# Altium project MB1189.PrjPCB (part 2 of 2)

## Sheet Arduino_ Connectors.SchDoc: Arduino Uno connector
size A4; Date: 9/24/2014; Author: P.A.; CompanyName: STMicroelectronics; Organization: Microcontrollers Division; Address1: 12, Rue Jules HOROWITZ; Address2: 38019 Grenoble; Address3: FRANCE; DocumentNumber: 12; Revision: B-07; SheetNumber: 12; SheetTotal: 13; Project: STM32F469I-DISCO
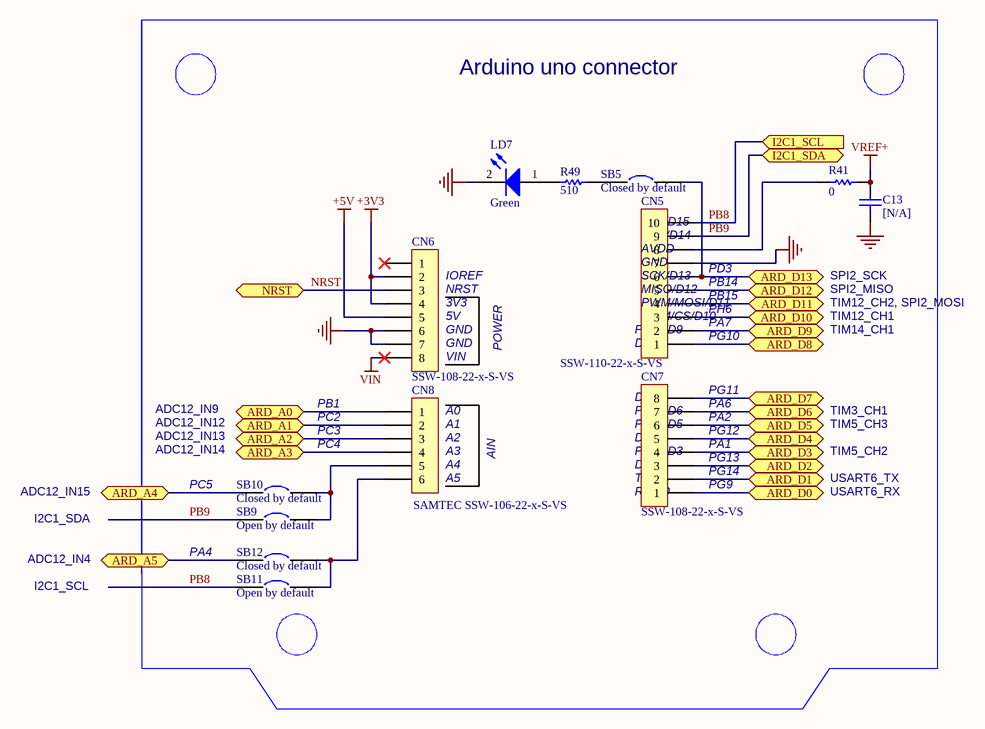
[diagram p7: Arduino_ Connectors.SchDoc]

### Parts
C13  [N/A]  [0603C]
CN5  SSW-110-22-x-S-VS  [SSW-110-22-X-S-VS]
CN6  SSW-108-22-x-S-VS  [SSW-108-22-X-S-VS]
CN7  SSW-108-22-x-S-VS  [SSW-108-22-X-S-VS]
CN8  SAMTEC SSW-106-22-x-S-VS  [SSW-106-22-X-S-VS]
LD7  Green  [0603D]
R41  0  [0603R]
R49  510  [0603R]
SB5  Closed by default  [SB_0603]
SB9  Open by default  [SB_0603]
SB10  Closed by default  [SB_0603]
SB11  Open by default  [SB_0603]
SB12  Closed by default  [SB_0603]

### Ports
ARD_A0 (bidir), ARD_A1 (bidir), ARD_A2 (bidir), ARD_A3 (bidir), ARD_A4 (bidir), ARD_A5 (bidir), ARD_D0 (bidir), ARD_D1 (bidir), ARD_D2 (bidir), ARD_D3 (bidir), ARD_D4 (bidir), ARD_D5 (bidir), ARD_D6 (bidir), ARD_D7 (bidir), ARD_D8 (bidir), ARD_D9 (bidir), ARD_D10 (bidir), ARD_D11 (bidir), ARD_D12 (bidir), ARD_D13 (bidir), I2C1_SCL (in), I2C1_SDA (bidir), NRST (bidir)

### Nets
+3V3: CN6.2 CN6.4
+5V: CN6.5
GND: C13.1 CN5.7 CN6.6 CN6.7 LD7.2(K)
VIN: CN6.8
VREF+: C13.2 R41.1
NRST: CN6.3 ; port NRST
PA1: CN7.4 ; port ARD_D3
PA2: CN7.6 ; port ARD_D5
PA4: SB12.1 ; port ARD_A5
PA6: CN7.7 ; port ARD_D6
PA7: CN5.2 ; port ARD_D9
PB1: CN8.1 ; port ARD_A0
PB8: CN5.10 SB11.1 ; port I2C1_SCL  [project net I2C1_SCL]
PB9: CN5.9 SB9.1 ; port I2C1_SDA  [project net I2C1_SDA]
PB14: CN5.5 ; port ARD_D12
PB15: CN5.4 ; port ARD_D11
PC2: CN8.2 ; port ARD_A1
PC3: CN8.3 ; port ARD_A2
PC4: CN8.4 ; port ARD_A3
PC5: SB10.1 ; port ARD_A4
PD3: CN5.6 SB5.2 ; port ARD_D13
PG9: CN7.1 ; port ARD_D0
PG10: CN5.1 ; port ARD_D8
PG11: CN7.8 ; port ARD_D7
PG12: CN7.5 ; port ARD_D4
PG13: CN7.3 ; port ARD_D2
PG14: CN7.2 ; port ARD_D1
PH6: CN5.3 ; port ARD_D10
NetCN5_8: CN5.8 R41.2
NetCN8_5: CN8.5 SB9.2 SB10.2
NetCN8_6: CN8.6 SB11.2 SB12.2
NetLD7_1: LD7.1(A) R49.2
NetR49_1: R49.1 SB5.1

Not connected (* = marked no-connect by the designer): CN6 1*

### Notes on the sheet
- Arduino uno connector
- (near CN5) SDA/D14
- SCL/D15
- (near CN5) AVDD
- (near CN6) IOREF
- (near CN6) NRST
- (near CN6) 3V3
- (near CN5) SCK/D13
- (near CN5) MISO/D12
- (near CN5) PWM/MOSI/D11
- (near CN5) GND
- (near CN5) PH6
- (near CN5) PB15
- (near CN5) PB14
- (near CN5) PD3
- TIM12_CH2, SPI2_MOSI
- SPI2_MISO
- SPI2_SCK
- (near CN6) 5V
- (near CN6) GND
- (near CN6) VIN
- POWER
- (near CN5) D8
- (near CN5) PWM/D9
- (near CN5) PWM/CS/D10
- (near CN5) PG10
- (near CN5) PA7
- TIM14_CH1
- TIM12_CH1
- ADC12_IN14
- ADC12_IN13
- ADC12_IN12
- ADC12_IN9
- PB1
- PC2
- PC3
- PC4
- (near CN8) A0
- (near CN8) A1
- (near CN8) A2
- (near CN7) D4
- (near CN7) PWM/D5
- (near CN7) PWM/D6
- (near CN7) D7
- (near CN7) PA1
- (near CN7) PG12
- (near CN7) PA2
- (near CN7) PA6
- PG11
- TIM5_CH3
- TIM3_CH1
- ADC12_IN15
- I2C1_SDA
- PC5
- (near CN8) A3
- (near CN8) A4
- (near CN8) A5
- AIN
- (near CN7) RX/D0
- (near CN7) TX/D1
- (near CN7) D2
- (near CN7) PWM/D3
- (near CN7) PG9
- (near CN7) PG14
- (near CN7) PG13
- USART6_RX
- USART6_TX
- TIM5_CH2
- ADC12_IN4
- PA4
- I2C1_SCL

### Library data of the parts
C13 = Cap: Capacitor; Value: 10nF; Ordered by: Subcon; Fitted: NO
CN5 = Header 10X1_Female: Header, 10-Pin, Single row,female; Manuf_1: SAMTEC; Ordered by: Subcon; Silkscreen: pin names as in schematic
CN6 CN7 = Header 8X1_Female: Header, 8-Pin, Single row,female; Manuf_1: SAMTEC; Ordered by: Subcon; Silkscreen: pin names as in schematic
CN8 = Header 6X1_Female: Header, 6-Pin, Single row,female SMD; Ordered by: Subcon; Silkscreen: pin names as in schematic
LD7 = LED2: Typical RED, GREEN, YELLOW, AMBER GaAs LED; Ordered by: Subcon; ECCN_US/EU: EAR99/NEC
R41 R49 = Res1: Resistor; Value: 1K; Ordered by: Subcon
SB5 SB10 SB12 = Circuit Breaker: Ordered by: Subcon; Comments: Solder bridge
SB9 SB11 = Circuit Breaker: Ordered by: Subcon; Comments: Solder bridge; Fitted: NO

## Sheet DSI_LCD.SchDoc: 4 inch DSI LCD board
size A4; Date: 9/24/2014; Author: P.A.; CompanyName: STMicroelectronics; Organization: Microcontrollers Division; Address1: 12, Rue Jules HOROWITZ; Address2: 38019 Grenoble; Address3: FRANCE; DocumentNumber: 8; Revision: B-07; SheetNumber: 8; SheetTotal: 13; Project: STM32F469I-DISCO
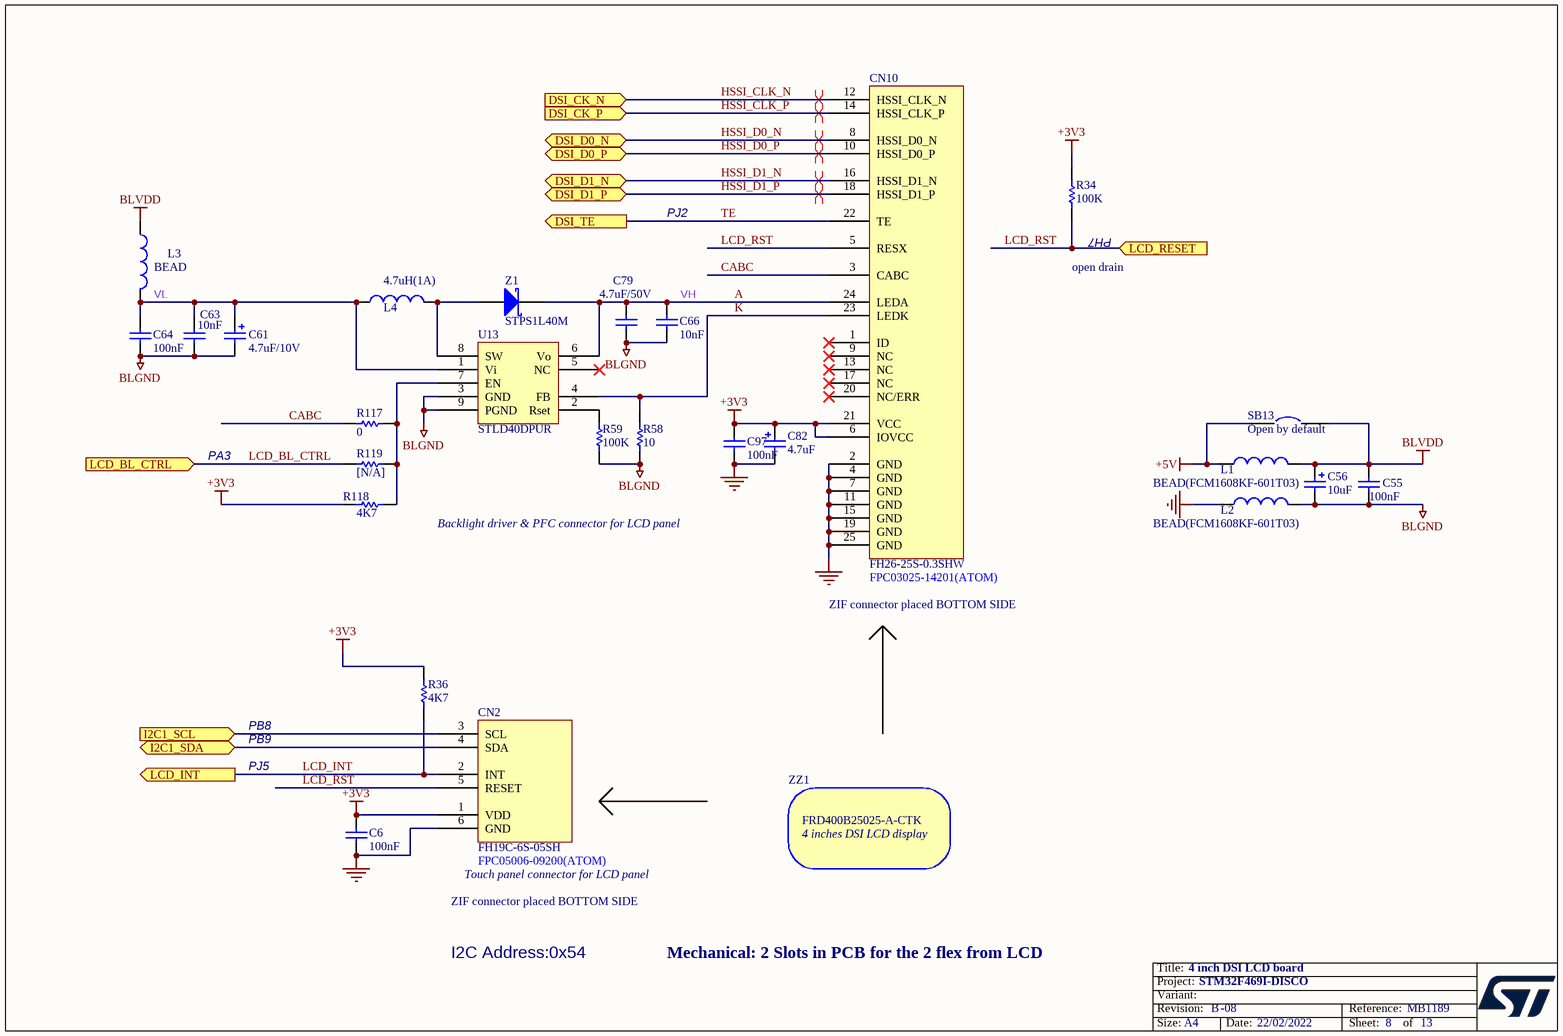
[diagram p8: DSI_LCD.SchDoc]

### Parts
C6  100nF  [0402C]
C55  100nF  [0402C]
C56  10uF  [TAN-A]
C61  4.7uF/10V  [1206C]
C63  10nF  [0603C]
C64  100nF  [0402C]
C66  10nF  [0603C]
C79  4.7uF/50V  [1206C]
C82  4.7uF  [TAN-A]
C97  100nF  [0402C]
CN2  FH19C-6S-05SH  [FH19C-6S-0R5SH_FPC_CPT]
CN10  FH26-25S-0.3SHW  [FPC25_FPC03025-1420]
L1  BEAD(FCM1608KF-601T03)  [0603L]
L2  BEAD(FCM1608KF-601T03)  [0603L]
L3  BEAD  [0603L]
L4  4.7uH(1A)  [1210L]
R34  100K  [0402R]
R36  4K7  [0603R]
R58  10  [0603R]
R59  100K  [0603R]
R117  0  [0603R]
R118  4K7  [0603R]
R119  [N/A]  [0603R]
SB13  Open by default  [SB_0603]
U13  STLD40DPUR  [SON8_0R65_3X3]
Z1  STPS1L40M  [DO-216AA]
ZZ1  FRD400B25025-A-CTK

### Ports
DSI_CK_N (in), DSI_CK_P (in), DSI_D0_N (bidir), DSI_D0_P (bidir), DSI_D1_N (bidir), DSI_D1_P (bidir), DSI_TE (out), I2C1_SCL (in), I2C1_SDA (bidir), LCD_BL_CTRL (in), LCD_INT (out), LCD_RESET (in)

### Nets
+3V3: C6.2 C82.1 C97.2 CN2.1(VDD) CN10.6(IOVCC) CN10.21(VCC) R34.1 R36.1 R118.2
+5V: L1.1 SB13.1
BLGND: C55.2 C56.2 C61.2 C63.1 C64.1 C66.1 C79.2 L2.2 R58.1 R59.2 U13.3(GND) U13.9(PGND)
BLVDD: C55.1 C56.1 L1.2 L3.1 SB13.2
GND: C6.1 C82.2 C97.1 CN2.6(GND) CN10.2(GND) CN10.4(GND) CN10.7(GND) CN10.11(GND) CN10.15(GND) CN10.19(GND) CN10.25(GND) L2.1
A: C66.2 C79.1 CN10.24(LEDA) U13.6(Vo) Z1.2(K)  [also labelled VH]
CABC: CN10.3(CABC) R117.2
HSSI_CLK_N: CN10.12(HSSI_CLK_N) ; port DSI_CK_N
HSSI_CLK_P: CN10.14(HSSI_CLK_P) ; port DSI_CK_P
HSSI_D0_N: CN10.8(HSSI_D0_N) ; port DSI_D0_N
HSSI_D0_P: CN10.10(HSSI_D0_P) ; port DSI_D0_P
HSSI_D1_N: CN10.16(HSSI_D1_N) ; port DSI_D1_N
HSSI_D1_P: CN10.18(HSSI_D1_P) ; port DSI_D1_P
I2C1_SCL: CN2.3(SCL) ; port I2C1_SCL
I2C1_SDA: CN2.4(SDA) ; port I2C1_SDA
K: CN10.23(LEDK) R58.2 U13.4(FB)
LCD_BL_CTRL: R119.2 ; port LCD_BL_CTRL
LCD_INT: CN2.2(INT) R36.2 ; port LCD_INT
LCD_RST: CN2.5(RESET) CN10.5(RESX) R34.2 ; port LCD_RESET
TE: CN10.22(TE) ; port DSI_TE  [project net PJ2]
VL: C61.1 C63.2 C64.2 L3.2 L4.1 U13.1(Vi)
NetL4_2: L4.2 U13.8(SW) Z1.1(A)
NetR59_1: R59.1 U13.2(Rset)
NetR117_1: R117.1 R118.1 R119.1 U13.7(EN)

Not connected (* = marked no-connect by the designer): CN10 1(ID)* 9(NC)* 13(NC)* 17(NC)* 20(NC/ERR)*; U13 5(NC)*

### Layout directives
differential pair: HSSI_CLK_N, HSSI_CLK_P, HSSI_D0_N, HSSI_D0_P, HSSI_D1_N, HSSI_D1_P

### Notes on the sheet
- PJ2
- (near R34) PH7
- open drain
- PA3
- Backlight driver & PFC connector for LCD panel
- (near CN10) FPC03025-14201(ATOM)
- ZIF connector placed BOTTOM SIDE
- PB9
- PB8
- PJ5
- (near ZZ1) 4 inches DSI LCD display
- (near CN2) Touch panel connector for LCD panel
- (near CN2) FPC05006-09200(ATOM)
- I2C Address:0x54
- Mechanical: 2 Slots in PCB for the 2 flex from LCD

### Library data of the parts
C6 C63 C64 C66 C79 C97 = CAP: Capacitor; Value: 100pF; Ordered by: Subcon
C55 = Cap: Capacitor; Value: 10nF; Ordered by: Subcon
C56 = Cap Pol1: Polarized Capacitor (Radial); Ordered by: Subcon
C61 C82 = Cap Pol1: Polarized Capacitor (Radial); Value: 100pF; Ordered by: Subcon
CN2 = FH19C-6S-05SH: ZIF connector placed bottom side; Manuf_1: ATOM; Manuf_2: Hirose; Manuf_Part_1: FPC05006-09200; Ordered by: Subcon; Silkscreen: TS
CN10 = FH26-25S-0.3SHW: ZIF connector placed bottom side; Manuf_1: ATOM; Manuf_Part_1: FPC03025-14201; Manuf_2: Hirose; Ordered by: Subcon; Comments: Hirose FH26-25S-0.3SHW; Silkscreen: DSI LCD
L1-L4 = Inductor: Value: 100uH; Ordered by: Subcon
R34 R36 R58 R59 R117 R118 = Res1: Resistor; Value: 1K; Ordered by: Subcon
R119 = Res1: Resistor; Value: 1K; Ordered by: Subcon; Fitted: NO
SB13 = Circuit Breaker: as SB9 on sheet Arduino_ Connectors
U13 = STLD40DPMR: Ordered by: ST; Ref St: 9176009; ECCN_US/EU: EAR99/NEC
Z1 = D Schottky: Schottky Diode; Code - JEDEC: DO-214-AA; Ordered by: ST; Ref St: 9151085; ECCN_US/EU: EAR99/NEC
ZZ1 = BoM_Item: 4 inches DSI LCD with touch screen; Manuf_1: Frida; Ordered by: Subcon; Comments: 4 inches DSI LCD display; ECCN_US/EU: EAR99/NEC

## Sheet QSPI.SchDoc: QSPI
size A4; Date: 9/24/2014; Author: P.A.; CompanyName: STMicroelectronics; Organization: Microcontrollers Division; Address1: 12, Rue Jules HOROWITZ; Address2: 38019 Grenoble; Address3: FRANCE; DocumentNumber: 10; Revision: B-07; SheetNumber: 10; SheetTotal: 13; Project: STM32F469I-DISCO
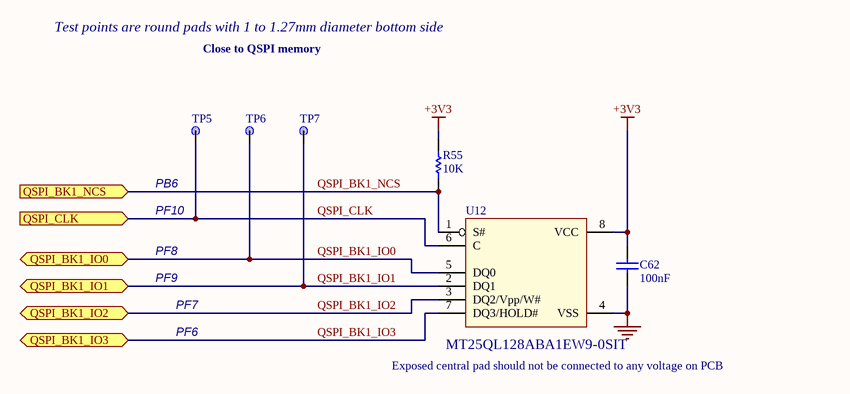
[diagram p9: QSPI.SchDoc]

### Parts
C62  100nF  [0402C]
R55  10K  [0402R]
TP5  TP  [TP_C40]  (value not drawn)
TP6  TP  [TP_C40]  (value not drawn)
TP7  TP  [TP_C40]  (value not drawn)
U12  MT25QL128ABA1EW9-0SIT  [DFN8_1R27_6X8_TP4R8X5R8]

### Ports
QSPI_BK1_IO0 (bidir), QSPI_BK1_IO1 (bidir), QSPI_BK1_IO2 (bidir), QSPI_BK1_IO3 (bidir), QSPI_BK1_NCS (in), QSPI_CLK (in)

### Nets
+3V3: C62.1 R55.2 U12.8(VCC)
GND: C62.2 U12.4(VSS)
QSPI_BK1_IO0: TP6.1 U12.5(DQ0) ; port QSPI_BK1_IO0  [project net PF8]
QSPI_BK1_IO1: TP7.1 U12.2(DQ1) ; port QSPI_BK1_IO1  [project net PF9]
QSPI_BK1_IO2: U12.3(DQ2/Vpp/W#) ; port QSPI_BK1_IO2  [project net PF7]
QSPI_BK1_IO3: U12.7(DQ3/HOLD#) ; port QSPI_BK1_IO3  [project net PF6]
QSPI_BK1_NCS: R55.1 U12.1(S#) ; port QSPI_BK1_NCS  [project net PB6]
QSPI_CLK: TP5.1 U12.6(C) ; port QSPI_CLK  [project net PF10]

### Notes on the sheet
- Test points are round pads with 1 to 1.27mm diameter bottom side
- Close to QSPI memory
- (near TP5) PB6
- PF10
- PF8
- PF9
- PF7
- PF6
- (near U12) Exposed central pad should not be connected to any voltage on PCB

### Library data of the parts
C62 = Cap: as C55 on sheet DSI_LCD
R55 = Res_10K_1%_0402: Resistor; Manuf_Part_1: RC0402FR-0710KL; Manuf_1: YAGEO; Ordered by: Subcon
TP5-TP7 = TP: Ordered by: Subcon
U12 = N25Q128A13EF840E: 128Mb, 3V, Multiple I/O Serial Flash Memory, Quad/Dual; Manuf_1: MICRON; Ordered by: Subcon

## Sheet AUDIO2.SchDoc: Audio Codec and Microphone MEMS
size A4; Date: 9/24/2014; Author: P.A.; CompanyName: STMicroelectronics; Organization: Microcontrollers Division; Address1: 12, Rue Jules HOROWITZ; Address2: 38019 Grenoble; Address3: FRANCE; DocumentNumber: 7; Revision: B-07; SheetNumber: 7; SheetTotal: 13; Project: STM32F469I-DISCO
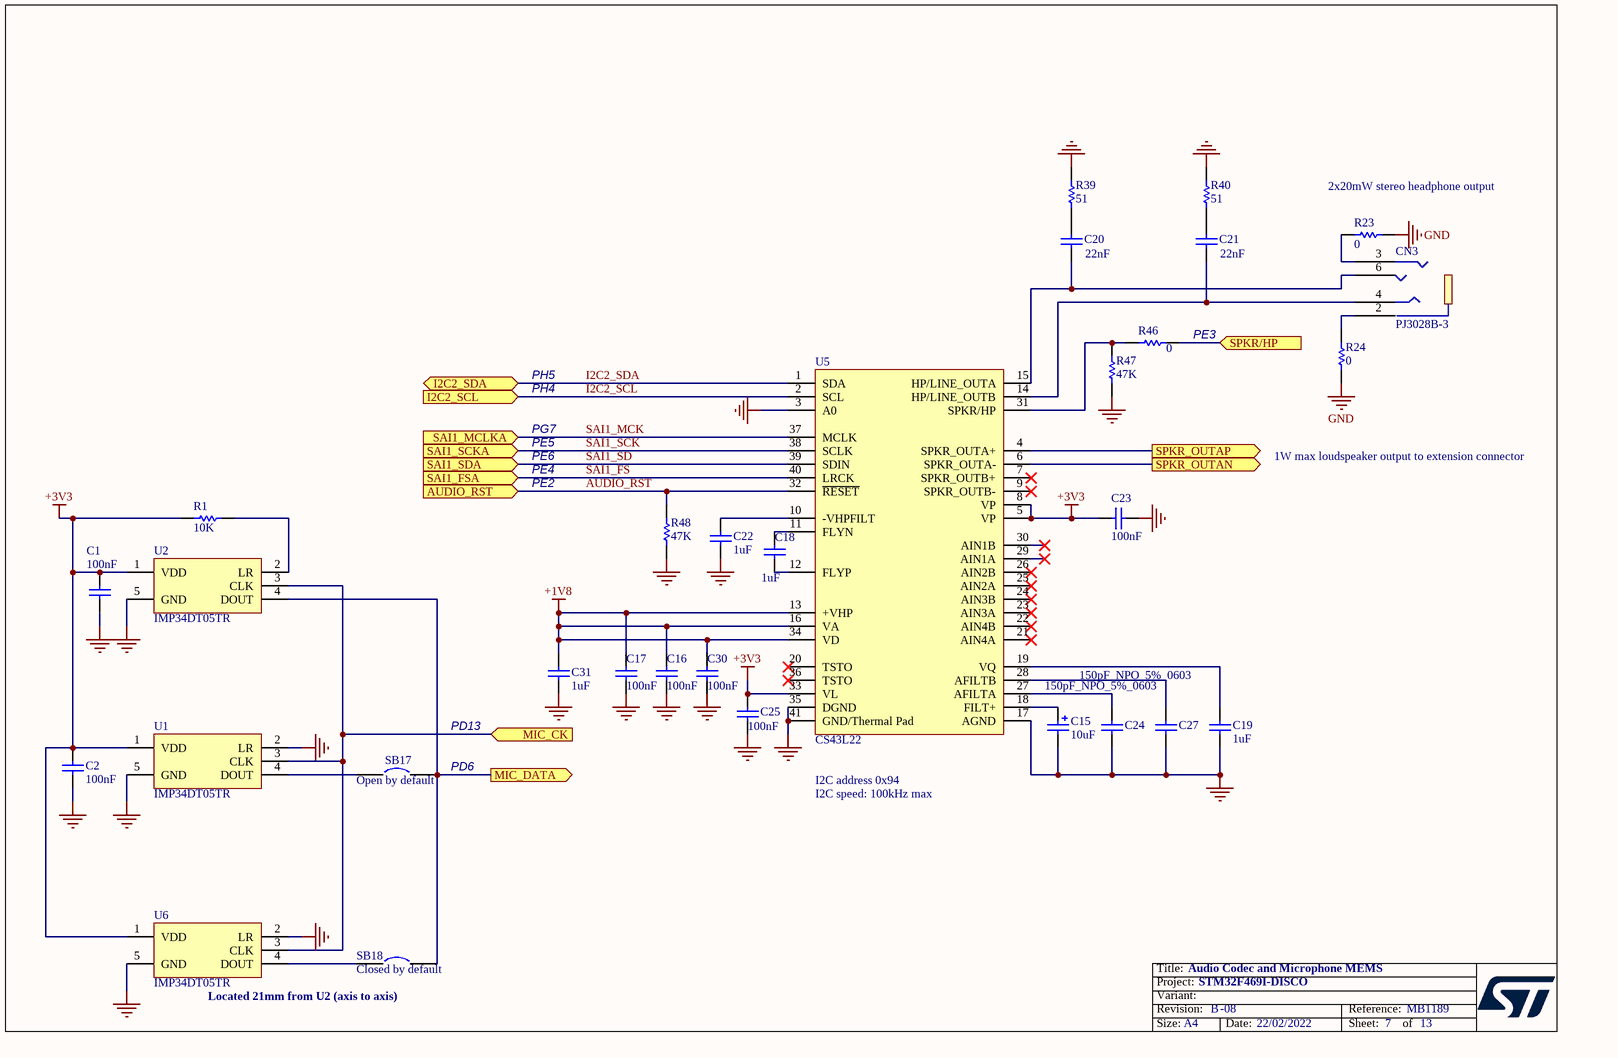
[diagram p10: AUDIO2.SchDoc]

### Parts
C1  100nF  [0402C]
C2  100nF  [0402C]
C15  10uF  [TAN-A]
C16  100nF  [0402C]
C17  100nF  [0402C]
C18  1uF  [0603C]
C19  1uF  [0603C]
C20  22nF  [0603C]
C21  22nF  [0603C]
C22  1uF  [0603C]
C23  100nF  [0402C]
C24  150pF_NPO_5%_0603  [0603C]
C25  100nF  [0402C]
C27  150pF_NPO_5%_0603  [0603C]
C30  100nF  [0402C]
C31  1uF  [0603C]
CN3  PJ3028B-3  [PJ3028B]
R1  10K  [0603R]
R23  0  [0603R]
R24  0  [0603R]
R39  51  [0402R]
R40  51  [0402R]
R46  0  [0603R]
R47  47K  [0603R]
R48  47K  [0603R]
SB17  Open by default  [SB_0603]
SB18  Closed by default  [SB_0603]
U1  IMP34DT05TR  [MP34DT01TR]
U2  IMP34DT05TR  [MP34DT01TR]
U5  CS43L22  [QFN40_0R5_6X6]
U6  IMP34DT05TR  [MP34DT01TR]

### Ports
AUDIO_RST (in), I2C2_SCL (in), I2C2_SDA (bidir), MIC_CK (in), MIC_DATA (out), SAI1_FSA (in), SAI1_MCLKA (in), SAI1_SCKA (in), SAI1_SDA (in), SPKR/HP (in), SPKR_OUTAN (out), SPKR_OUTAP (out)

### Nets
+1V8: C16.1 C17.1 C30.1 C31.1 U5.13(+VHP) U5.16(VA) U5.34(VD)
+3V3: C1.2 C2.2 C23.2 C25.1 R1.2 U1.1(VDD) U2.1(VDD) U5.5(VP) U5.8(VP) U5.33(VL) U6.1(VDD)
GND: C1.1 C2.1 C15.2 C16.2 C17.2 C19.1 C22.1 C23.1 C24.1 C25.2 C27.1 C30.2 C31.2 R23.2 R24.2 R39.2 R40.2 R47.2 R48.1 U1.2(LR) U1.5(GND) U2.5(GND) U5.3(A0) U5.17(AGND) U5.35(DGND) U5.41(GND/Thermal_Pad) U6.2(LR) U6.5(GND)
AUDIO_RST: R48.2 U5.32(~{RESET}) ; port AUDIO_RST
I2C2_SCL: U5.2(SCL) ; port I2C2_SCL
I2C2_SDA: U5.1(SDA) ; port I2C2_SDA
PD6: SB17.2 SB18.2 U2.4(DOUT) ; port MIC_DATA
PE3: R46.2 ; port SPKR/HP
SAI1_FS: U5.40(LRCK) ; port SAI1_FSA  [project net PE4]
SAI1_MCK: U5.37(MCLK) ; port SAI1_MCLKA  [project net PG7]
SAI1_SCK: U5.38(SCLK) ; port SAI1_SCKA  [project net PE5]
SAI1_SD: U5.39(SDIN) ; port SAI1_SDA  [project net PE6]
NetC15_1: C15.1 U5.18(FILT+)
NetC18_1: C18.1 U5.11(FLYN)
NetC18_2: C18.2 U5.12(FLYP)
NetC19_2: C19.2 U5.19(VQ)
NetC20_1: C20.1 CN3.6 U5.15(HP/LINE_OUTA)
NetC20_2: C20.2 R39.1
NetC21_1: C21.1 CN3.4 U5.14(HP/LINE_OUTB)
NetC21_2: C21.2 R40.1
NetC22_2: C22.2 U5.10(-VHPFILT)
NetC24_2: C24.2 U5.27(AFILTA)
NetC27_2: C27.2 U5.28(AFILTB)
NetCN3_2: CN3.2 R24.1
NetCN3_3: CN3.3 R23.1
NetCN12_15: U5.6(SPKR_OUTA-) ; port SPKR_OUTAN
NetCN12_16: U5.4(SPKR_OUTA+) ; port SPKR_OUTAP
NetR1_1: R1.1 U2.2(LR)
NetR46_1: R46.1 R47.1 U5.31(SPKR/HP)
NetR87_1: U1.3(CLK) U2.3(CLK) U6.3(CLK) ; port MIC_CK
NetSB17_1: SB17.1 U1.4(DOUT)
NetSB18_1: SB18.1 U6.4(DOUT)

Not connected (* = marked no-connect by the designer): U5 7(SPKR_OUTB+)* 9(SPKR_OUTB-)* 20(TSTO)* 21(AIN4A)* 22(AIN4B)* 23(AIN3A)* 24(AIN3B)* 25(AIN2A)* 26(AIN2B)* 29(AIN1A)* 30(AIN1B)* 36(TSTO)*

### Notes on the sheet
- (near R23) 2x20mW stereo headphone output
- PH5
- (near R46) PE3
- PE5
- PG7
- PH4
- PE6
- PE4
- PE2
- 1W max loudspeaker output to extension connector
- PD13
- (near SB17) PD6
- I2C address 0x94
- I2C speed: 100kHz max
- Located 21mm from U2 (axis to axis)

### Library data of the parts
C1 C2 = Cap: as C55 on sheet DSI_LCD
C15 = Cap Pol1: as C56 on sheet DSI_LCD
C16-C19 C22 C23 C25 C30 C31 = CAP: as C6 on sheet DSI_LCD
C20 C21 = Cap_22nF_X7R_10%_0603: Capacitor,22nF,50V,X7R,10%,0603,YAGEO; Manuf_Part_1: CC0603KRX7R9BB223; Ordered by: Subcon
C24 C27 = Cap_150pF_NPO_5%_0603: Capacitor,150pF,50V,NPO,5%,0603,YAGEO; Order: CC0603JRNPO9BN151; Ordered by: Subcon
CN3 = PJ3028B-3: Manuf_1: QIAOD; Ordered by: Subcon; Silkscreen: AUDIO JACK
R1 = Res_0_5%_0402: Resistor; Manuf_Part_1: RC0402JR-070RL; Manuf_1: YAGEO; Value: 0; Order: 2363467; Ordered by: Subcon
R23 R24 R46-R48 = Res1: Resistor; Value: 1K; Ordered by: Subcon
R39 R40 = Res_51_1%_0402: Resistor; Manuf_Part_1: RC0402FR-0751RL; Manuf_1: YAGEO; Order: 311-51.0LRTR-ND; Ordered by: Subcon
SB17 = Circuit Breaker: as SB9 on sheet Arduino_ Connectors
SB18 = Circuit Breaker: as SB5 on sheet Arduino_ Connectors
U1 U2 U6 = MP34DT01TR: MEMS audio sensor; Manuf_1: ST
U5 = CS43L22: Low Power, Stereo DAC w/Headphone & Speaker Amps; Manuf_1: Cirrus; Order: CS43L22-CNZ; ECCN_US/EU: EAR99/NEC; Ordered by: Subcon

## Sheet USB_OTG_FS.SchDoc: USB_OTG_FS
size A4; Date: 9/24/2014; Author: P.A.; CompanyName: STMicroelectronics; Organization: Microcontrollers Division; Address1: 12, Rue Jules HOROWITZ; Address2: 38019 Grenoble; Address3: FRANCE; DocumentNumber: 11; Revision: B-07; SheetNumber: 11; SheetTotal: 13; Project: STM32F469I-DISCO
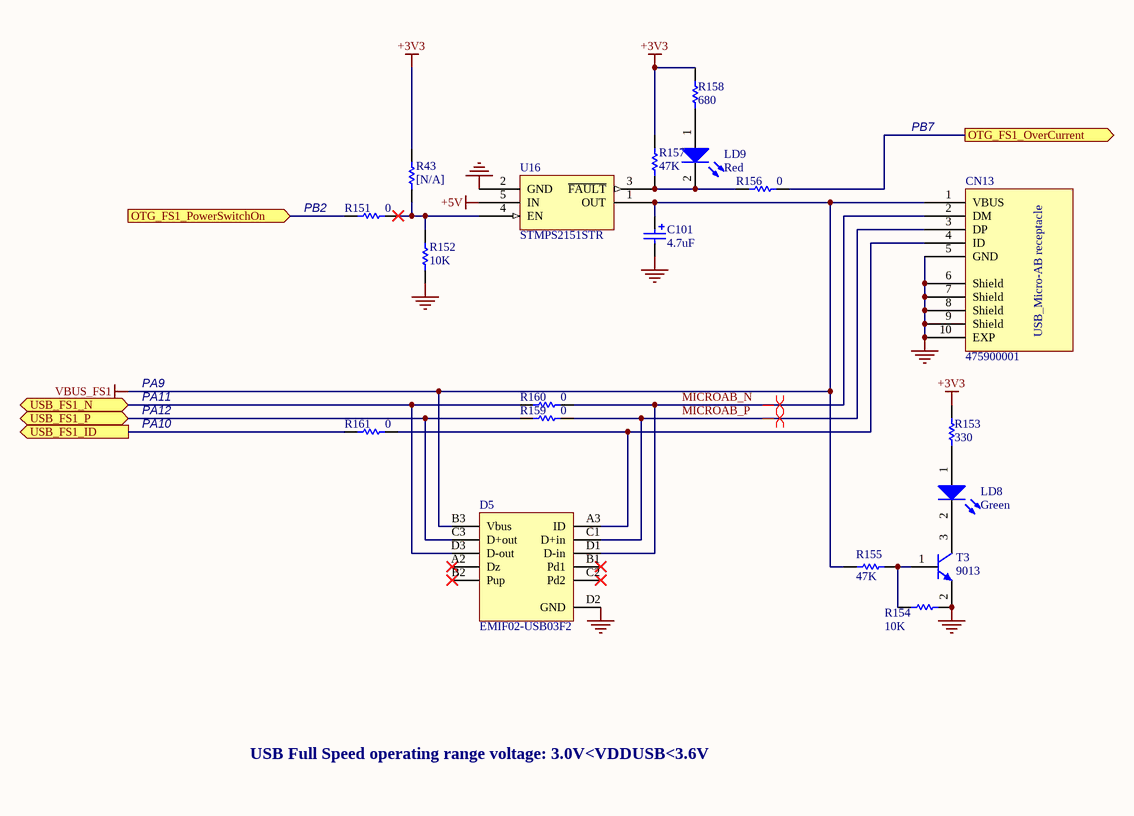
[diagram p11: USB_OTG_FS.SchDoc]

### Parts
C101  4.7uF  [TAN-A]
CN13  475900001  [MOLEX_47590001]
D5  EMIF02-USB03F2  [BGA11_0R5_1R57X2R07]
LD8  Green  [0603D]
LD9  Red  [0603D]
R43  [N/A]  [0603R]
R151  0  [0603R]
R152  10K  [0402R]
R153  330  [0603R]
R154  10K  [0603R]
R155  47K  [0603R]
R156  0  [0603R]
R157  47K  [0603R]
R158  680  [0603R]
R159  0  [0603R]
R160  0  [0603R]
R161  0  [0603R]
T3  9013  [SOT-23]
U16  STMPS2151STR  [SOT23-5]

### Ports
OTG_FS1_OverCurrent (out), OTG_FS1_PowerSwitchOn (in), USB_FS1_ID (out), USB_FS1_N (bidir), USB_FS1_P (bidir)

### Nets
+3V3: R43.1 R153.2 R157.1 R158.2
+5V: U16.5(IN)
GND: C101.2 CN13.5(GND) CN13.6(Shield) CN13.7(Shield) CN13.8(Shield) CN13.9(Shield) CN13.10(EXP) D5.D2(GND) R152.1 R154.1 T3.2(E) U16.2(GND)
VBUS_FS1: C101.1 CN13.1(VBUS) D5.B3(Vbus) R155.1 U16.1(OUT)
MICROAB_N: CN13.2(DM) D5.D1(D-in) R160.1
MICROAB_P: CN13.3(DP) D5.C1(D+in) R159.1
PA10: R161.2 ; port USB_FS1_ID
PB2: R151.2 ; port OTG_FS1_PowerSwitchOn
PB7: R156.1 ; port OTG_FS1_OverCurrent
USB_FS1_N: D5.D3(D-out) R160.2 ; port USB_FS1_N
USB_FS1_P: D5.C3(D+out) R159.2 ; port USB_FS1_P
NetCN13_4: CN13.4(ID) D5.A3(ID) R161.1
NetLD8_1: LD8.1(A) R153.1
NetLD8_2: LD8.2(K) T3.3(C)
NetLD9_1: LD9.1(A) R158.1
NetLD9_2: LD9.2(K) R156.2 R157.2 U16.3(~{FAULT})
NetR43_2: R43.2 R151.1 R152.2 U16.4(EN)
NetR154_2: R154.2 R155.2 T3.1(B)

Not connected (* = marked no-connect by the designer): D5 A2(Dz)* B1(Pd1)* B2(Pup)* C2(Pd2)*

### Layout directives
differential pair: MICROAB_N, MICROAB_P

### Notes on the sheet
- PB7
- (near R151) PB2
- PA9
- PA10
- PA11
- PA12
- USB Full Speed operating range voltage: 3.0V<VDDUSB<3.6V

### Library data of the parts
C101 = Cap Pol1: Polarized Capacitor (Radial); Value: 47uF; Ordered by: Subcon
CN13 = 475900001: Manuf_1: MOLEX; Ordered by: Subcon; Silkscreen: USB USER
D5 = EMIF02-USB03F2: 2-line IPAD, EMI filter including ESD protection; Manuf_1: ST; ECCN_US/EU: EAR99/NEC; Ref St: 9179037
LD8 = LED2: Typical RED, GREEN, YELLOW, AMBER GaAs LED; Ordered by: Subcon; ECCN_US/EU: EAR99/NEC; Silkscreen: VBUS
LD9 = LED2: Typical RED, GREEN, YELLOW, AMBER GaAs LED; Ordered by: Subcon; ECCN_US/EU: EAR99/NEC; Silkscreen: FAULT
R43 = Res1: as R119 on sheet DSI_LCD
R151 R152 R156 R158-R161 = Res1: Resistor; Value: 1K; Ordered by: Subcon
R153-R155 R157 = res1: Resistor; Value: 1K; Ordered by: Subcon
T3 = NPN: NPN Bipolar Transistor; Manuf_Part_1: MMBT9013; Code - JEDEC: TO-226-AA; Ordered by: Subcon; ECCN_US/EU: EAR99/NEC
U16 = STMPS2141STR: Ordered by: ST; Ref St: 9159009; ECCN_US/EU: EAR99/NEC

## Sheet ExtensionConnector.SchDoc: Extension Connectors
size A4; Date: 9/24/2014; Author: P.A.; CompanyName: STMicroelectronics; Organization: Microcontrollers Division; Address1: 12, Rue Jules HOROWITZ; Address2: 38019 Grenoble; Address3: FRANCE; DocumentNumber: 4; Revision: B-07; SheetNumber: 4; SheetTotal: 13; Project: STM32F469I-DISCO
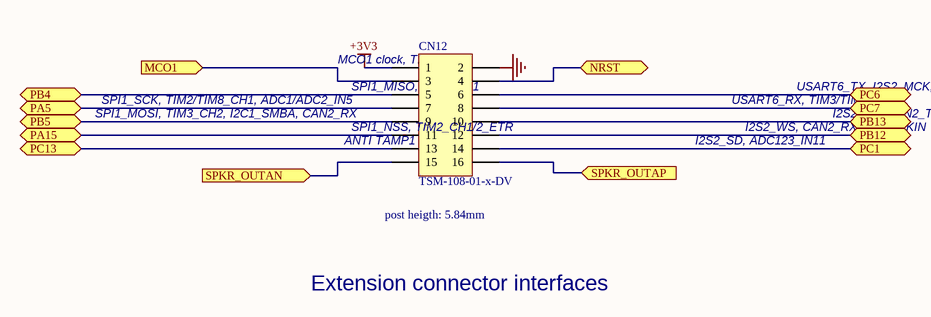
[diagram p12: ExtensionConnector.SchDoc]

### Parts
CN12  TSM-108-01-x-DV  [TSM-108-01-X-DV]

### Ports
MCO1 (in), NRST (bidir), PA5 (bidir), PA15 (bidir), PB4 (bidir), PB5 (bidir), PB12 (bidir), PB13 (bidir), PC1 (bidir), PC6 (bidir), PC7 (bidir), PC13 (bidir), SPKR_OUTAN (in), SPKR_OUTAP (in)

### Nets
+3V3: CN12.1
GND: CN12.2
NRST: CN12.4 ; port NRST
PA5: CN12.7 ; port PA5
PA8: CN12.3 ; port MCO1
PA15: CN12.11 ; port PA15
PB4: CN12.5 ; port PB4
PB5: CN12.9 ; port PB5
PB12: CN12.12 ; port PB12
PB13: CN12.10 ; port PB13
PC1: CN12.14 ; port PC1
PC6: CN12.6 ; port PC6
PC7: CN12.8 ; port PC7
PC13: CN12.13 ; port PC13
NetCN12_15: CN12.15 ; port SPKR_OUTAN
NetCN12_16: CN12.16 ; port SPKR_OUTAP

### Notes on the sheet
- MCO1 clock, TIM1_CH1
- SPI1_MISO, TIM3_CH1
- USART6_TX, I2S2_MCK, TIM3/TIM8_CH1
- SPI1_MOSI, TIM3_CH2, I2C1_SMBA, CAN2_RX
- SPI1_SCK, TIM2/TIM8_CH1, ADC1/ADC2_IN5
- ANTI TAMP1
- SPI1_NSS, TIM2_CH1/2_ETR
- I2S2_SD, ADC123_IN11
- USART6_RX, TIM3/TIM8_CH2
- I2S2_WS, CAN2_RX, TIM1_BKIN
- I2S2_CK, CAN2_TX, USART3_CTS, TIM1_CH1N
- (near CN12) post heigth: 5.84mm
- Extension connector interfaces

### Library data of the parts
CN12 = Header 8X2: Header, 8-Pin, Dual row; Manuf_1: SAMTEC; Ordered by: Subcon; Silkscreen: EXT

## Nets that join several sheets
+1V8: Power (C32.1 U8.2 U8.4), AUDIO2 (7 pins)
+3V3: Memory (28 pins), Peripherals (15 pins), Power (C41.1 JP5.1 SB8.2 U8.3), ST_LINK_V2-1 (R33.1), MCU (7 pins), Arduino_ Connectors (CN6.2 CN6.4), DSI_LCD (9 pins), QSPI (C62.1 R55.2 U12.8), AUDIO2 (11 pins), USB_OTG_FS (R43.1 R153.2 R157.1 R158.2), ExtensionConnector (CN12.1)
+5V: Power (6 pins), ST_LINK_V2-1 (D1.1), Arduino_ Connectors (CN6.5), DSI_LCD (L1.1 SB13.1), USB_OTG_FS (U16.5)
E5V: Power (C35.1 JP2.1 U10.2 U10.4), ST_LINK_V2-1 (D2.1)
GND: Top (H1.1 H2.1 H3.1 H4.1), Memory (28 pins), Peripherals (7 pins), Power (12 pins), ST_LINK_V2-1 (34 pins), MCU (57 pins), Arduino_ Connectors (5 pins), DSI_LCD (12 pins), QSPI (C62.2 U12.4), AUDIO2 (28 pins), USB_OTG_FS (12 pins), ExtensionConnector (CN12.2)
U5V_ST_LINK: Power (JP2.3), ST_LINK_V2-1 (C14.2 U4.6 U4.7)
VBUS_FS1: Power (JP2.5), ST_LINK_V2-1 (D3.1), MCU (U14.E15), USB_OTG_FS (5 pins)
VDD_MCU: Power (JP5.2), MCU (40 pins)
VIN: Power (C36.1 U10.3), Arduino_ Connectors (CN6.8)
VREF+: MCU (C78.2 C80.1 R123.2 U14.P1), Arduino_ Connectors (C13.2 R41.1)
A0: Memory (U11.G8), MCU (U14.D2)
A1: Memory (U11.G9), MCU (U14.E2)
A2: Memory (U11.F7), MCU (U14.G2)
A3: Memory (U11.F3), MCU (U14.H2)
A4: Memory (U11.G1), MCU (U14.J2)
A5: Memory (U11.G2), MCU (U14.K3)
A6: Memory (U11.G3), MCU (U14.M6)
A7: Memory (U11.H1), MCU (U14.N6)
A8: Memory (U11.H2), MCU (U14.P6)
A9: Memory (U11.J3), MCU (U14.M8)
A10: Memory (U11.G7), MCU (U14.N7)
A11: Memory (U11.H9), MCU (U14.M7)
A14: Memory (U11.J7), MCU (U14.N12)
A15: Memory (U11.H8), MCU (U14.N11)
AUDIO_RST: MCU (U14.A3), AUDIO2 (R48.2 U5.32)
D0: Memory (TP4.1 U11.R8), MCU (TP1.1 U14.L12)
D1: Memory (U11.N7), MCU (U14.K13)
D2: Memory (U11.R9), MCU (U14.B12)
D3: Memory (U11.N8), MCU (U14.C12)
D4: Memory (U11.P9), MCU (U14.R8)
D5: Memory (U11.M8), MCU (U14.N9)
D6: Memory (U11.M7), MCU (U14.P9)
D7: Memory (U11.L8), MCU (U14.R9)
D8: Memory (U11.L2), MCU (U14.P10)
D9: Memory (U11.M3), MCU (U14.R10)
D10: Memory (U11.M2), MCU (U14.R12)
D11: Memory (U11.P1), MCU (U14.P11)
D12: Memory (U11.N2), MCU (U14.R11)
D13: Memory (U11.R1), MCU (U14.L15)
D14: Memory (U11.N3), MCU (U14.L14)
D15: Memory (U11.R2), MCU (U14.K15)
D16: Memory (U11.E8), MCU (U14.P14)
D17: Memory (U11.D7), MCU (U14.N14)
D18: Memory (U11.D8), MCU (U14.P15)
D19: Memory (U11.B9), MCU (U14.N15)
D20: Memory (U11.C8), MCU (U14.M15)
D21: Memory (U11.A9), MCU (U14.E12)
D22: Memory (U11.C7), MCU (U14.E13)
D23: Memory (U11.A8), MCU (U14.D13)
D24: Memory (U11.A2), MCU (U14.E14)
D25: Memory (U11.C3), MCU (U14.D14)
D26: Memory (U11.A1), MCU (U14.C14)
D27: Memory (U11.C2), MCU (U14.C13)
D28: Memory (U11.B1), MCU (U14.D6)
D29: Memory (U11.D2), MCU (U14.D4)
D30: Memory (U11.D3), MCU (U14.E4)
D31: Memory (U11.E2), MCU (U14.D5)
HSSI_CLK_N: MCU (U14.H13), DSI_LCD (CN10.12)
HSSI_CLK_P: MCU (U14.H12), DSI_LCD (CN10.14)
HSSI_D0_N: MCU (U14.J13), DSI_LCD (CN10.8)
HSSI_D0_P: MCU (U14.J12), DSI_LCD (CN10.10)
HSSI_D1_N: MCU (U14.F13), DSI_LCD (CN10.16)
HSSI_D1_P: MCU (U14.F12), DSI_LCD (CN10.18)
I2C1_SCL: Peripherals (CN11.3), MCU (R140.2 U14.A7), Arduino_ Connectors (CN5.10 SB11.1), DSI_LCD (CN2.3)
I2C1_SDA: Peripherals (CN11.1), MCU (R142.2 U14.B4), Arduino_ Connectors (CN5.9 SB9.1), DSI_LCD (CN2.4)
I2C2_SCL: MCU (R121.2 U14.H4), AUDIO2 (U5.2)
I2C2_SDA: MCU (R124.2 U14.J3), AUDIO2 (U5.1)
LCD_BL_CTRL: MCU (U14.R2), DSI_LCD (R119.2)
LCD_INT: MCU (U14.M14), DSI_LCD (CN2.2 R36.2)
LCD_RST: MCU (U14.N13), DSI_LCD (CN2.5 CN10.5 R34.2)
NetC26_1: ST_LINK_V2-1 (C26.1 R35.2), MCU (SB19.1)
NetCN9_8: Peripherals (CN9.8 R86.2), MCU (R135.2)
NetCN12_15: AUDIO2 (U5.6), ExtensionConnector (CN12.15)
NetCN12_16: AUDIO2 (U5.4), ExtensionConnector (CN12.16)
NetR87_1: MCU (R87.1), AUDIO2 (U1.3 U2.3 U6.3)
NetSB3_2: ST_LINK_V2-1 (SB3.2), MCU (SB7.1)
NRST: Peripherals (SB1.1), ST_LINK_V2-1 (SB2.2), MCU (U14.J1), Arduino_ Connectors (CN6.3), ExtensionConnector (CN12.4)
PA0: Peripherals (R18.2), MCU (U14.N3)
PA1: MCU (U14.N2), Arduino_ Connectors (CN7.4)
PA2: MCU (U14.P2), Arduino_ Connectors (CN7.6)
PA4: MCU (U14.N4), Arduino_ Connectors (SB12.1)
PA5: MCU (U14.P4), ExtensionConnector (CN12.7)
PA6: MCU (U14.P3), Arduino_ Connectors (CN7.7)
PA7: MCU (U14.R3), Arduino_ Connectors (CN5.2)
PA8: MCU (U14.F15), ExtensionConnector (CN12.3)
PA10: MCU (U14.D15), USB_OTG_FS (R161.2)
PA13: ST_LINK_V2-1 (R20.2 U3.27), MCU (U14.A15)
PA14: ST_LINK_V2-1 (U3.15 U3.26), MCU (U14.A14)
PA15: MCU (U14.A13), ExtensionConnector (CN12.11)
PB0: Peripherals (CN11.4), MCU (U14.R5)
PB1: MCU (U14.R4), Arduino_ Connectors (CN8.1)
PB2: MCU (U14.M5), USB_OTG_FS (R151.2)
PB4: MCU (U14.A9), ExtensionConnector (CN12.5)
PB5: MCU (U14.A8), ExtensionConnector (CN12.9)
PB6: MCU (U14.B6), QSPI (R55.1 U12.1)
PB7: MCU (U14.B5), USB_OTG_FS (R156.1)
PB10: ST_LINK_V2-1 (U3.13), MCU (U14.P12)
PB11: ST_LINK_V2-1 (U3.12), MCU (U14.R13)
PB12: MCU (U14.L13), ExtensionConnector (CN12.12)
PB13: MCU (U14.K14), ExtensionConnector (CN12.10)
PB14: MCU (U14.R14), Arduino_ Connectors (CN5.5)
PB15: MCU (U14.R15), Arduino_ Connectors (CN5.4)
PC0: Memory (TP2.1 U11.K8), MCU (U14.M2)
PC1: MCU (U14.M3), ExtensionConnector (CN12.14)
PC2: MCU (U14.M4), Arduino_ Connectors (CN8.2)
PC3: MCU (U14.L4), Arduino_ Connectors (CN8.3)
PC4: MCU (U14.N5), Arduino_ Connectors (CN8.4)
PC5: MCU (U14.P5), Arduino_ Connectors (SB10.1)
PC6: MCU (U14.H15), ExtensionConnector (CN12.6)
PC7: MCU (U14.G15), ExtensionConnector (CN12.8)
PC8: Peripherals (CN9.7 R114.2), MCU (U14.G14)
PC10: Peripherals (CN9.1 R120.2), MCU (U14.B14)
PC11: Peripherals (CN9.2 R116.2), MCU (U14.B13)
PC12: Peripherals (CN9.5), MCU (U14.A12)
PC13: MCU (U14.D1), ExtensionConnector (CN12.13)
PD2: Peripherals (CN9.3 R115.2), MCU (U14.D12)
PD3: MCU (U14.C11), Arduino_ Connectors (CN5.6 SB5.2)
PD4: Peripherals (R3.1), MCU (U14.D11)
PD5: Peripherals (R4.1), MCU (U14.C10)
PD6: MCU (U14.B11), AUDIO2 (SB17.2 SB18.2 U2.4)
PE0: Memory (U11.K9), MCU (U14.A6)
PE1: Memory (U11.K1), MCU (U14.A5)
PE3: MCU (U14.A2), AUDIO2 (R46.2)
PE4: MCU (U14.A1), AUDIO2 (U5.40)
PE5: MCU (U14.B1), AUDIO2 (U5.38)
PE6: MCU (U14.B2), AUDIO2 (U5.39)
PF6: MCU (U14.K2), QSPI (U12.7)
PF7: MCU (U14.K1), QSPI (U12.3)
PF8: MCU (U14.L3), QSPI (TP6.1 U12.5)
PF9: MCU (U14.L2), QSPI (TP7.1 U12.2)
PF10: MCU (U14.L1), QSPI (TP5.1 U12.6)
PF11: Memory (U11.J9), MCU (U14.P8)
PG2: Peripherals (R57.1), MCU (U14.M13)
PG6: Peripherals (R2.1), MCU (U14.J15)
PG7: MCU (U14.J14), AUDIO2 (U5.37)
PG8: Memory (TP3.1 U11.J1), MCU (U14.H14)
PG9: MCU (U14.D9), Arduino_ Connectors (CN7.1)
PG10: MCU (U14.C8), Arduino_ Connectors (CN5.1)
PG11: MCU (U14.B8), Arduino_ Connectors (CN7.8)
PG12: MCU (U14.C7), Arduino_ Connectors (CN7.5)
PG13: MCU (U14.B3), Arduino_ Connectors (CN7.3)
PG14: MCU (U14.A4), Arduino_ Connectors (CN7.2)
PG15: Memory (U11.K7), MCU (U14.B7)
PH2: Memory (U11.J2), MCU (U14.K4)
PH3: Memory (U11.J8), MCU (U14.J4)
PH6: MCU (U14.P13), Arduino_ Connectors (CN5.3)
PI4: Memory (U11.F8), MCU (U14.C3)
PI5: Memory (U11.F2), MCU (U14.D3)
PJ2: MCU (U14.P7), DSI_LCD (CN10.22)
PK3: Peripherals (R5.1), MCU (U14.D8)
USB_FS1_N: MCU (U14.C15), USB_OTG_FS (D5.D3 R160.2)
USB_FS1_P: MCU (U14.B15), USB_OTG_FS (D5.C3 R159.2)

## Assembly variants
F469NIH6: not fitted C4 C13 C26 CN4 R29 R31 R34 R43 R119 R144 R150 TP1 TP2 TP3 TP4 TP5 TP6 TP7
